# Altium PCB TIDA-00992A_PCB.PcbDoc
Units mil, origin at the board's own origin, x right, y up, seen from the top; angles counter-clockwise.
Board outline 1653.54 x 1259.84 mil, 2 copper layers (Top Layer, Bottom Layer), stack 62 mil thick; 32 components, 12 nets, 69 pads, 63 vias.
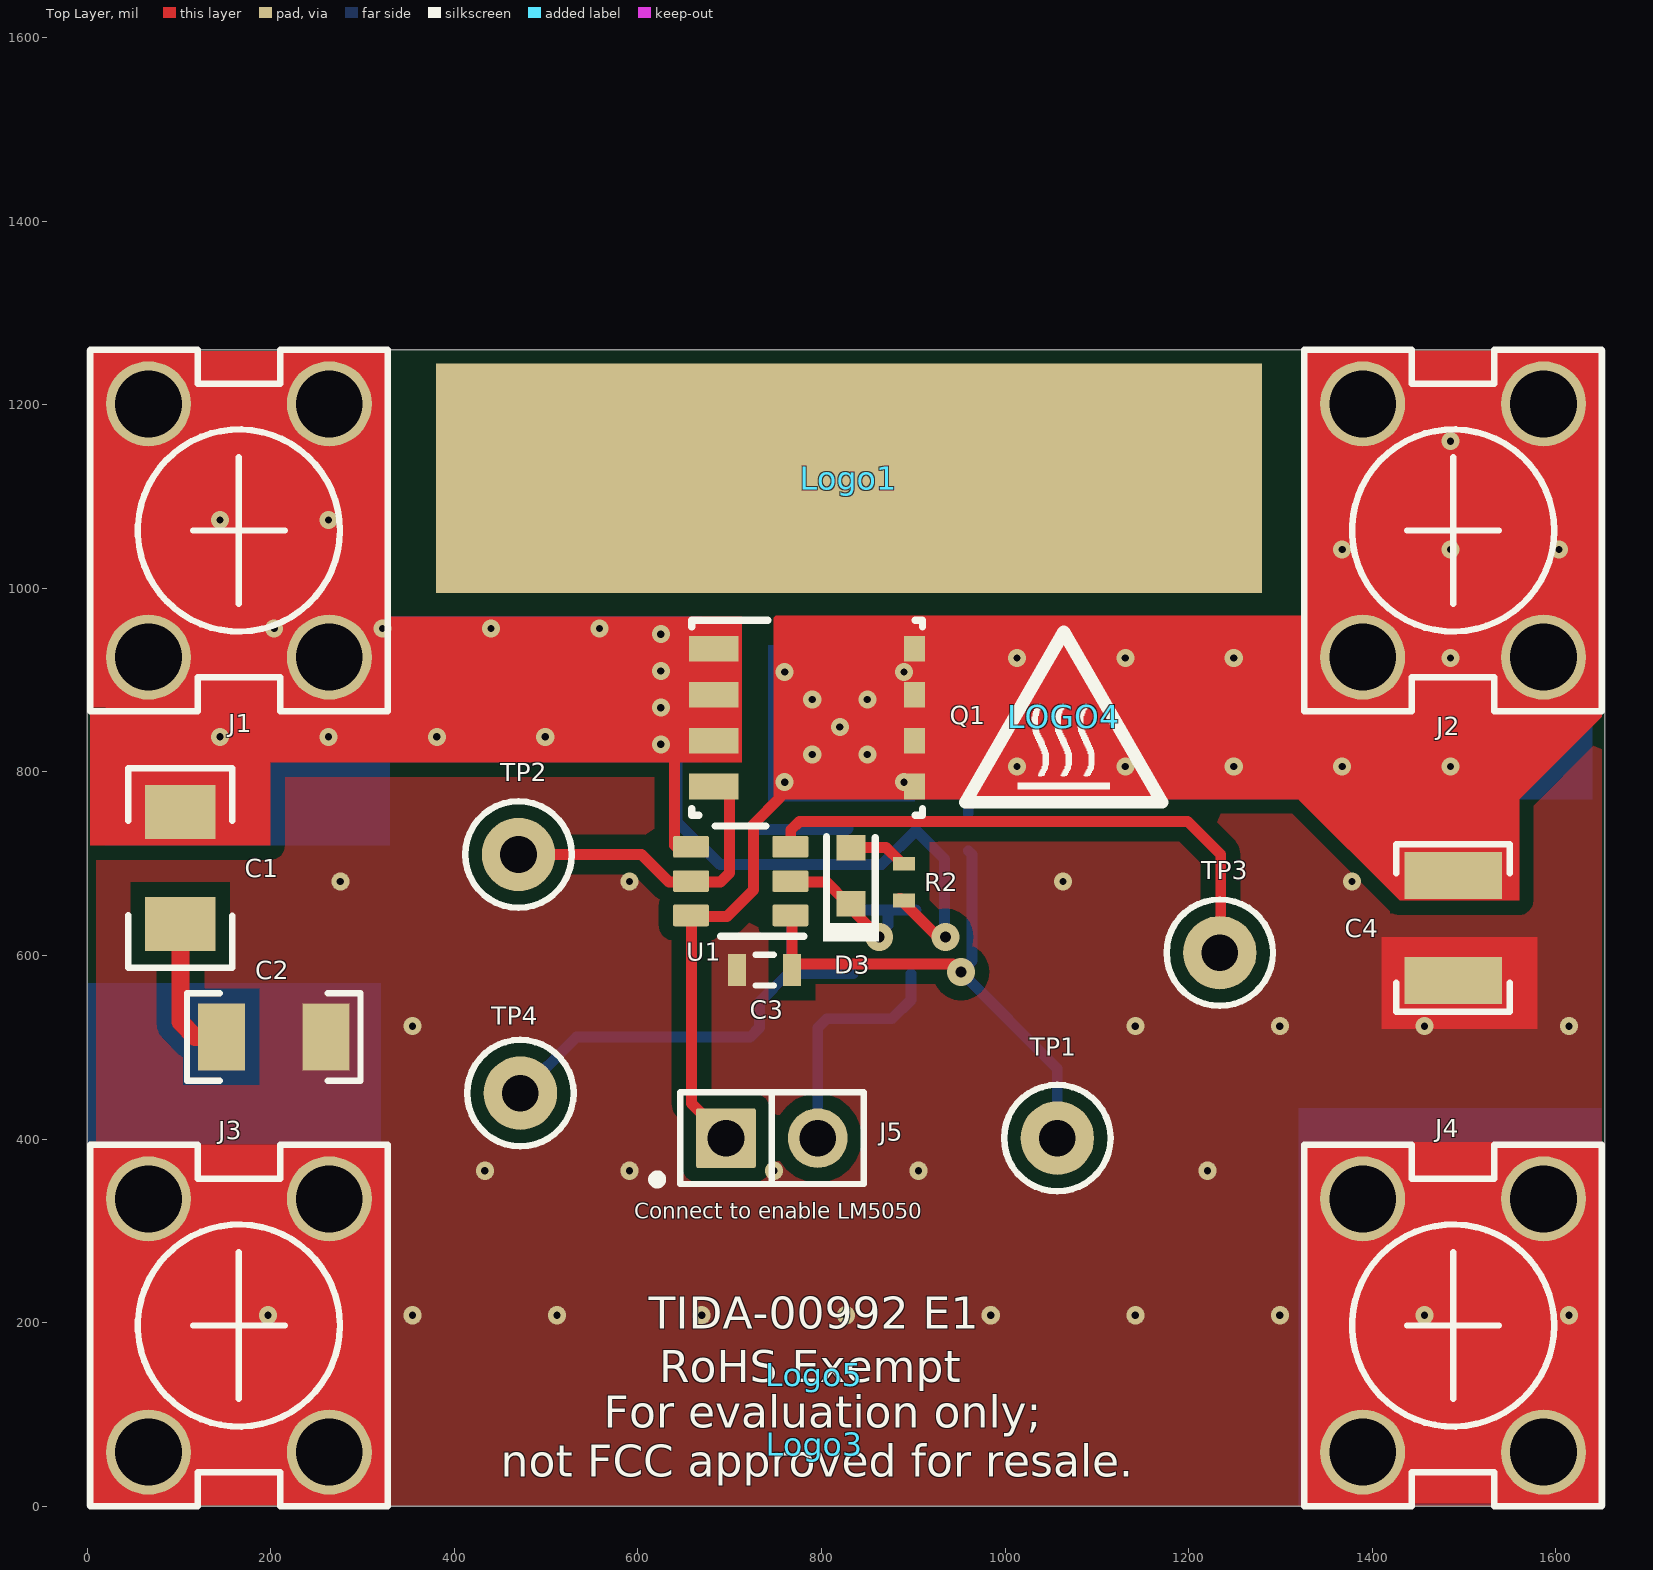
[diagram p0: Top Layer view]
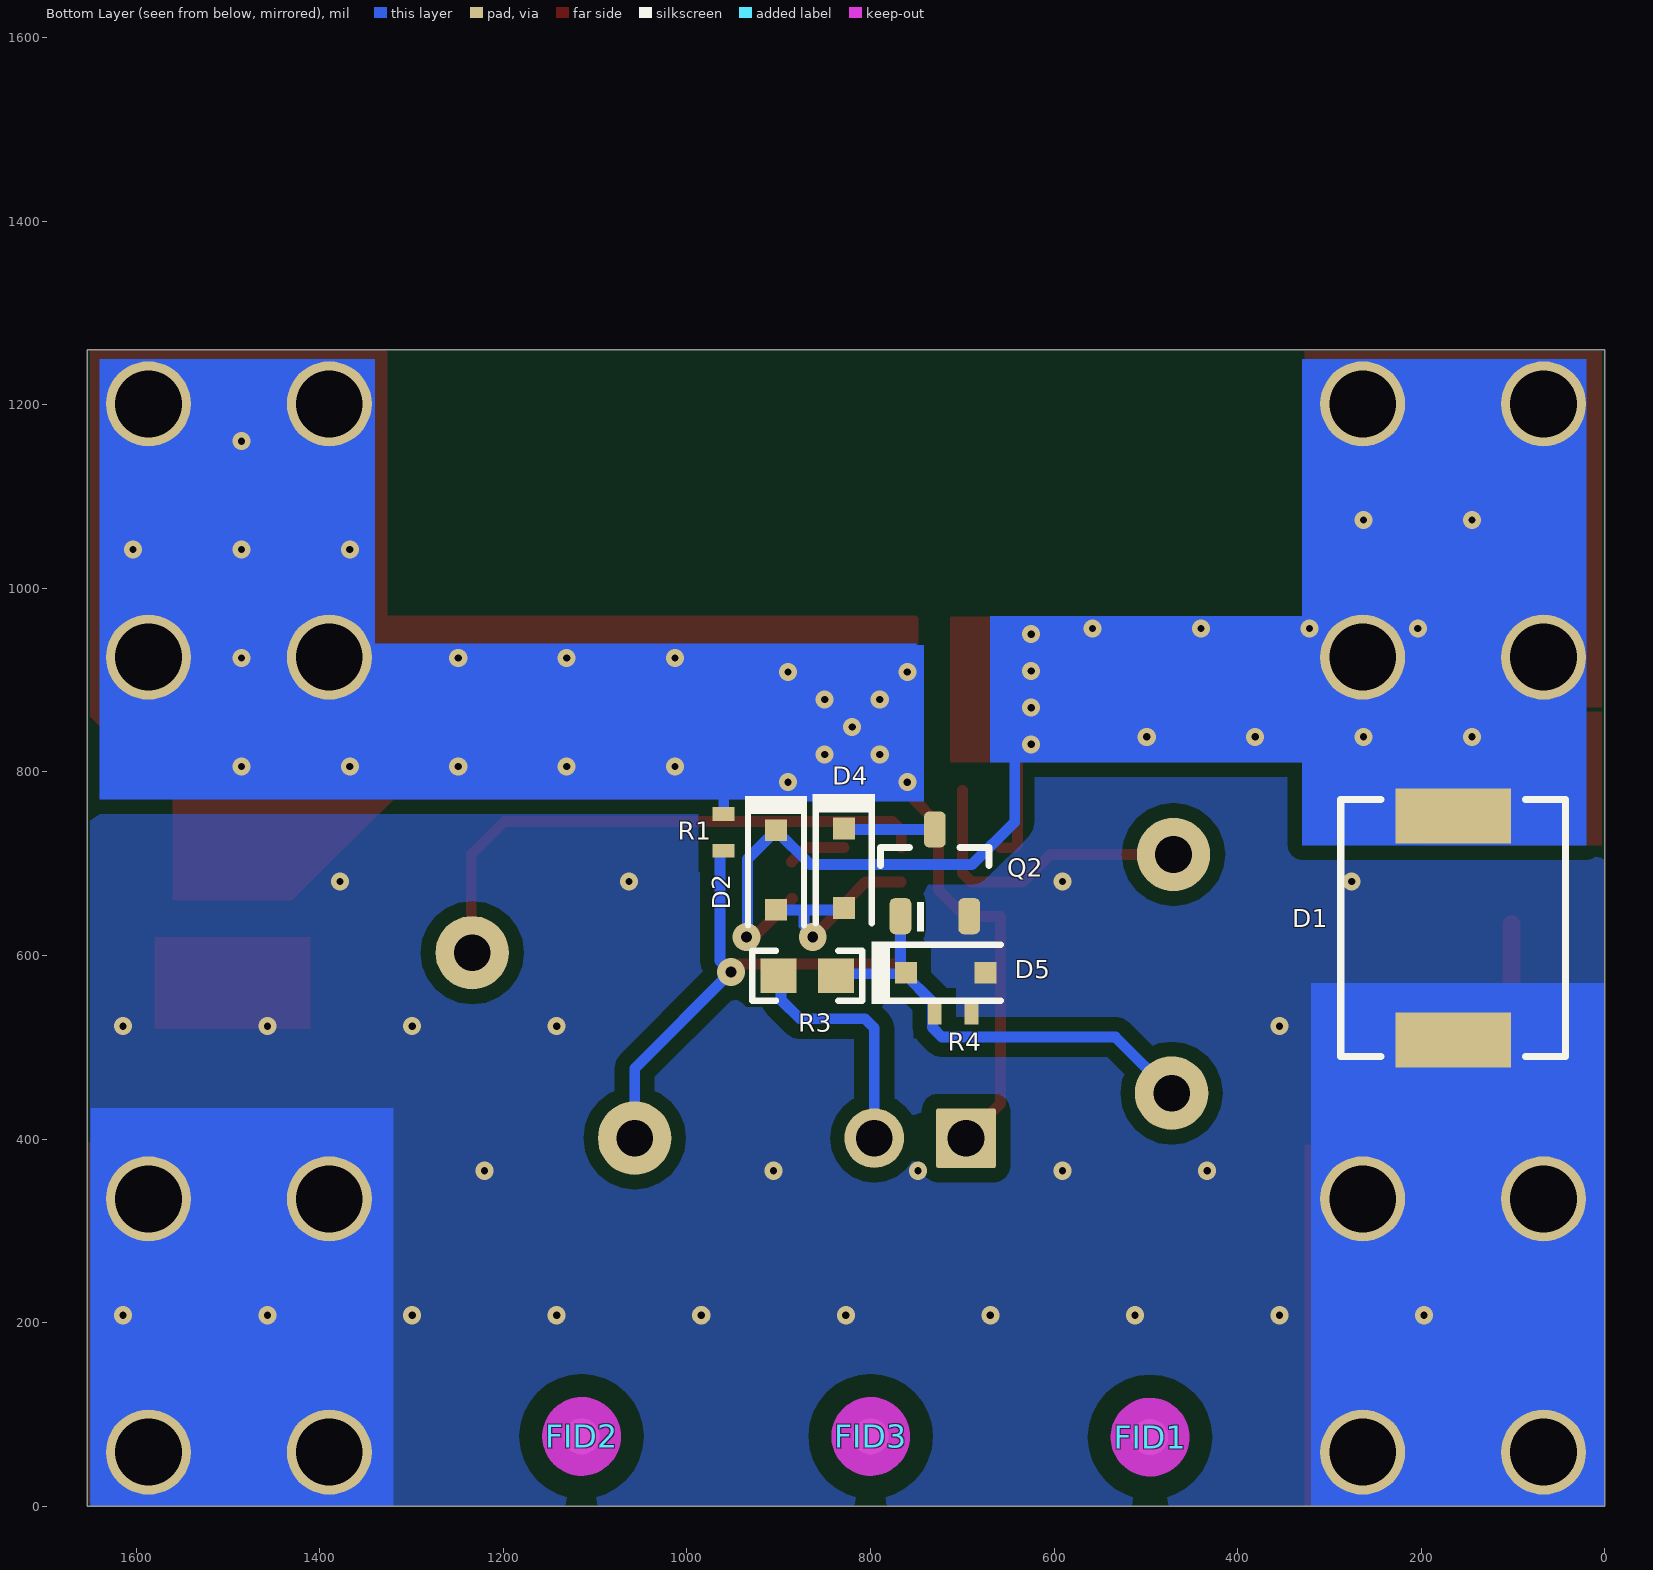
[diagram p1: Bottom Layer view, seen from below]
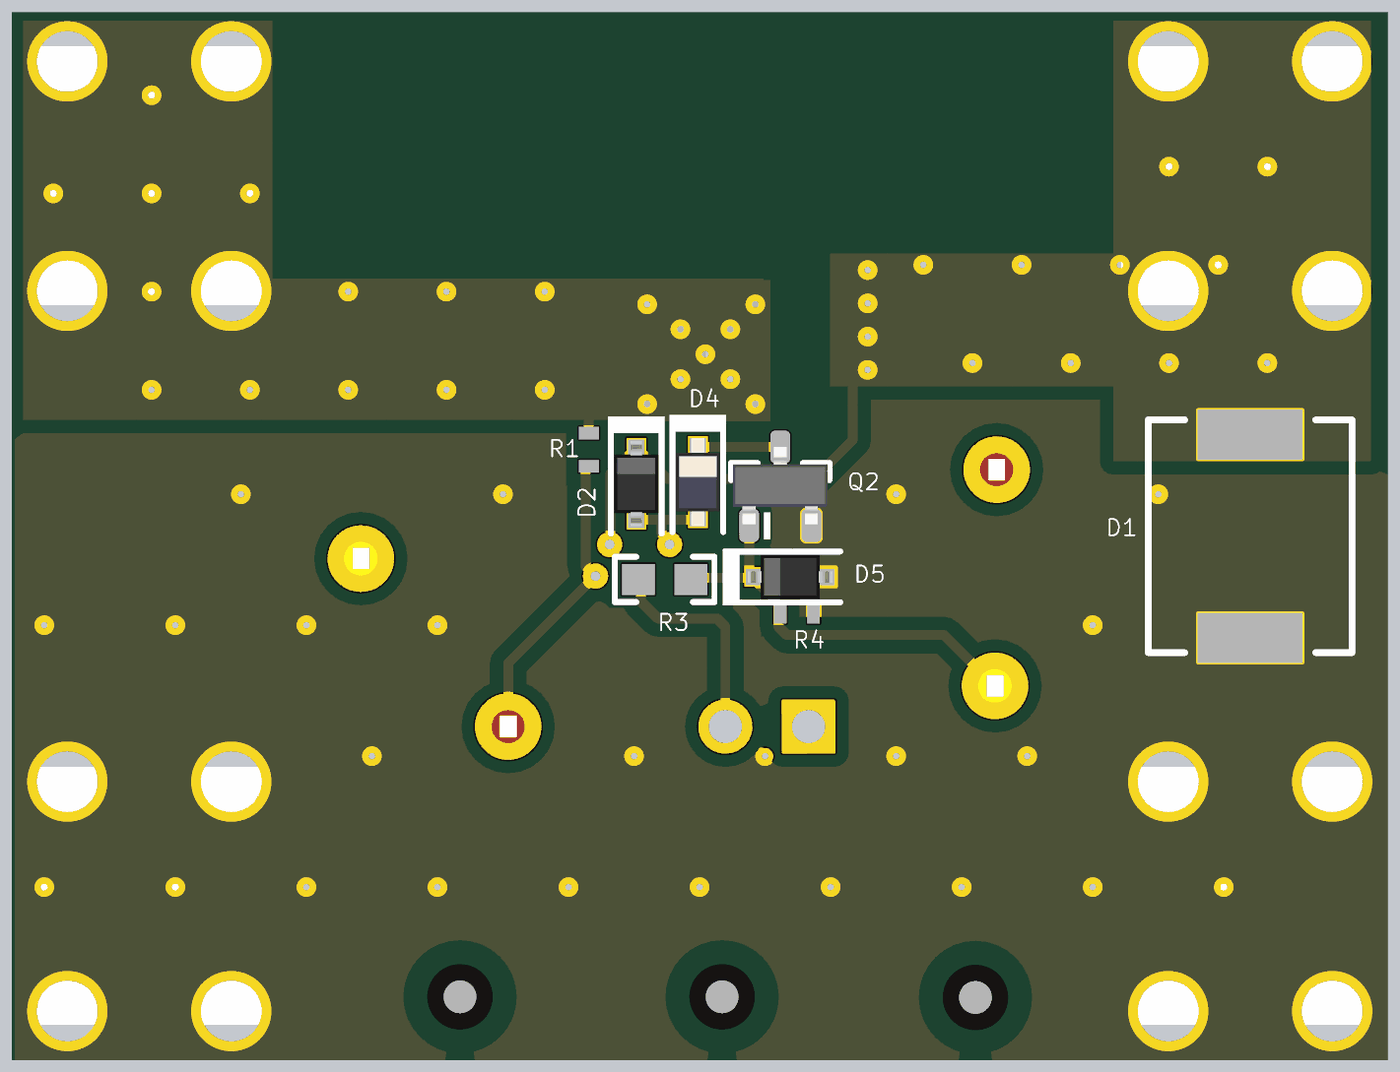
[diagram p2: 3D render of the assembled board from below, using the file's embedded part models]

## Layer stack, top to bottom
Top Solder: solder mask 0.4, Solder Resist, Dk 3.5
Top Layer: signal copper 1.4
Dielectric1: core 59.2, FR-4, Dk 4.8
Bottom Layer: signal copper 1.4
Bottom Solder: solder mask 0.4, Solder Resist, Dk 3.5

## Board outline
0,0 1653.54,0 1653.54,1259.84 0,1259.84

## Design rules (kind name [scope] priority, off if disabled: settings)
AcuteAngle [All] p1: minimum=4.50000000000000E+0001 checktracksonly=FALSE
AssemblyTestPointUsage [All] p1: valid=2
Clearance Clearance_Keepouts [((IsTrack Or IsArc) And Not InPoly) And IsFree and IsKeepOut vs ((IsTrack Or IsArc) And Not InPoly) And IsFree and IsKeepOut] p1: gap=0
Clearance Clearance_BoardEdge_MountingHoles [OnCopper and InComponentClass('Mounting Holes') vs IsKeepOut] p2: gap=40
Clearance Clearance_BoardEdge_Poly [OnCopper and InPoly vs IsKeepOut] p3: gap=25
Clearance Clearance_BoardEdge [OnCopper and Not InComponentClass('Logo') and not InComponentClass('FiducialMark') and not InRegion(1000,500,4000,800) and Not IsKeepout vs IsKeepOut] p4: gap=75
Clearance Clearance_Poly [InPolygon] p5: gap=15.75
Clearance [All] p6: gap=7.87
ComponentClearance ComponentClearance_MountingHoles_FiducialMarks [InComponentClass('Mounting Holes') vs InComponent('TP1')] p1: gap=0 collisioncheckmode=3 verticalgap=0 showdistances=FALSE
ComponentClearance ComponentClearance_Shunt [InComponentClass('Header') vs InComponentClass('Shunt')] p2: gap=0 collisioncheckmode=3 verticalgap=0 showdistances=FALSE
ComponentClearance ComponentClearance_Logo [InComponentClass('Logo')] p3: gap=19.68 collisioncheckmode=3 verticalgap=10 showdistances=FALSE
ComponentClearance ComponentClearance_ScrewToNut [(HasFootprint('NY PMS 440 0025 PH')) vs (HasFootprint('Keystone_1902C'))] p4: gap=5 collisioncheckmode=3 verticalgap=10 showdistances=FALSE
ComponentClearance ComponentClearance_MountingHoles [InComponentClass('Mounting Holes')] p5: gap=250 collisioncheckmode=3 verticalgap=100000 showdistances=FALSE
ComponentClearance ComponentClearance_SmallPassives [HasFootprint('0201*') or HasFootprint('0402*') or HasFootprint('0508') or HasFootprint('0603*') or HasFootprint('0612') or HasFootprint('0805*') or HasFootprint('0815*') or HasFootprint('0830*') or HasFootprint('1206*') or HasFootprint('1210*') or HasFootprint('1808*') or HasFootprint('1812*') or HasFootprint('1825*') or HasFootprint('2010*') or HasFootprint('2220*') or HasFootprint('2225*') or HasFootprint('2512*') or HasFootprint('2728*') or HasFootprint('3518*') vs HasFootprint('0201*') or HasFootprint('0402*') or HasFootprint('0508') or HasFootprint('0603*') or HasFootprint('0612') or HasFootprint('0805*') or HasFootprint('0815*') or HasFootprint('0830*') or HasFootprint('1206*') or HasFootprint('1210*') or HasFootprint('1808*') or HasFootprint('1812*') or HasFootprint('1825*') or HasFootprint('2010*') or HasFootprint('2220*') or HasFootprint('2225*') or HasFootprint('2512*') or HasFootprint('2728*') or HasFootprint('3518*')] p6: gap=19.68 collisioncheckmode=3 verticalgap=10 showdistances=FALSE
ComponentClearance ComponentClearance_THtoSMT [IsThruComponent vs IsSMTComponent] p7: gap=59.06 collisioncheckmode=3 verticalgap=30 showdistances=FALSE
ComponentClearance ComponentClearance_THtoTH [IsThruComponent vs IsThruComponent] p8: gap=118.11 collisioncheckmode=3 verticalgap=30 showdistances=FALSE
ComponentClearance [All] p9: gap=0 collisioncheckmode=3 verticalgap=10 showdistances=FALSE
DiffPairsRouting [All] p1: maxlimit=100 minlimit=10 mostfreqgap=10 toplayer_minwidth=15 toplayer_maxwidth=15 toplayer_prefwidth=15 bottomlayer_minwidth=15 bottomlayer_maxwidth=15 bottomlayer_prefwidth=15 maxuncoupledlength=1000
FabricationTestPointUsage TestPointUsage [All] p1: valid=2 allowmultiple=FALSE
FabricationTestpoint Testpoint [All] p1: side=3 testpointundercomponent=TRUE minsize=40 maxsize=100 preferedsize=60 minholesize=0 maxholesize=40 preferedholesize=32 testpointgrid=1 allowsidetop=TRUE allowsidebottom=TRUE usegrid=TRUE gridtolerance=0.01
FanoutControl Fanout_LCC [IsLCC] p1: bgadir=Out bgaviamode=Centered fanoutstyle=Auto fanoutdirection=Alternating viagrid=1 // Fanout_LCC (Default Rule)
FanoutControl Fanout_BGA [IsBGA] p2: bgadir=Out bgaviamode=Centered fanoutstyle=Auto fanoutdirection=Alternating viagrid=1 // Fanout_BGA (Default Rule)
FanoutControl Fanout_Default [All] p4: bgadir=Out bgaviamode=Centered fanoutstyle=Auto fanoutdirection=Alternating viagrid=1 // Fanout_Default (Default Rule)
FanoutControl Fanout_Small [(CompPinCount < 5)] p5: bgadir=Out bgaviamode=Centered fanoutstyle=Auto fanoutdirection=OutThenIn viagrid=1 // Fanout_Small (Default Rule)
HoleSize [All] p1: absolutevalues=TRUE maxlimit=251 minlimit=7.87 maxpercent=80.000 minpercent=20.000
MinimumAnnularRing MinimumAnnularRing_ThermalPadVias [IsVia and InAnyComponent] p1: minimumring=3.94
MinimumAnnularRing [All] p2: minimumring=5
MinimumSolderMaskSliver MinimumSolderMaskSliver_Logo [InComponentClass('Logo') vs InComponentClass('Logo')] p1: minsoldermaskwidth=0.7
MinimumSolderMaskSliver [All] p2: minsoldermaskwidth=4
PlaneConnect [All] p1: planeconnectstyle=Relief reliefexpansion=10 reliefentries=4 reliefconductorwidth=10 reliefairgap=10
PolygonConnect [All] p1: connectstyle=Direct reliefconductorwidth=10 reliefentries=4 polygonreliefangle="90 Angle" airgapwidth=10
RoutingVias ThermalPadVias [IsVia and InAnyComponent] p1: holewidth=7.87 width=19.68 viastyle="Through Hole" minholewidth=7.87 minwidth=19.68 maxholewidth=12.99 maxwidth=23.62
RoutingVias [All] p2: holewidth=16 width=34 viastyle="Through Hole" minholewidth=7.87 minwidth=19.68 maxholewidth=40 maxwidth=65
SilkToBoardRegionClearance [Not ((IsComment or IsDesignator) And (Hide <> 'False')) and not InRegion(1000,500,4000,800)] p1:
SilkToSilkClearance SilkToSilkClearance_Pb-FreeLogo [(HasFootprint('Pb-Free_Overlay_Medium') OR HasFootprint('Pb-Free_Overlay_Small')) vs (HasFootprint('Pb-Free_Overlay_Medium') OR HasFootprint('Pb-Free_Overlay_Small'))] p1: silktosilkclearance=0
SilkToSilkClearance [All] p2: silktosilkclearance=4
SilkToSolderMaskClearance SilkToComonentPadClearance [IsPad and InAnycomponent] p1: minsilkscreentomaskgap=0 clearancetoexposedcopper=TRUE
SilkToSolderMaskClearance "Silk to Solder Mask Opening" [All] p2: minsilkscreentomaskgap=0 clearancetoexposedcopper=TRUE
SolderMaskExpansion [All] p1: expansion=1.97
Width [All] p1: maxlimit=100 minlimit=6 preferedwidth=10 checkconnectedcopper=TRUE
15 further rules are at their usual default settings.

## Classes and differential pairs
component class Logo: Logo1
component class TIDA-00992A_Hardware: FID1 FID2 FID3 Logo1 Logo3 LOGO4 Logo5 LOGO?
component class FiducialMark: FID1 FID2 FID3
component class Header: J5
component class TIDA-00992A_AutomotiveReversePolarityProtection: C1 C2 C3 C4 D1 D2 D3 D4 D5 J1 J2 J3 J4 J5 Q1 Q2 R1 R2 R3 R4 TP1 TP2 TP3 TP4 U1

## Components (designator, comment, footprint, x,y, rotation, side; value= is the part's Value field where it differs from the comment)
C1 "VJ1206Y104KBBAT4X" 1206M 101.52,695.28 r270 top
C2 "VJ1206Y104KBBAT4X" 1206 203.32,511.34 r180 top
C3 "GRM188R72A104KA35J" 0603S 738,584 r180 top
C4 "GRM32ER71K475KE14L" 1210_270 1488.19,629.92 r270 top
D1 "1.5SMC33CA-E3/57T" DO-214AB-Bi 165.35,629.92 r90 bottom
D2 "BAS 170W E6327" sod-323 903,693 r270 bottom
D3 "LNJ337W83RA" LNJx37x8_Green 832,687 r90 top
D4 "PMEG6010CEJ,115" SOD-323F 829,695 r270 bottom
D5 "BZT52C9V1S-7-F" sod-323 718,581 r180 bottom
FID1 "Fiducial" Fiducial10-20 495.5,75.25 r180 bottom
FID2 "Fiducial" Fiducial10-20 1114.86,75.99 r180 bottom
FID3 "Fiducial" Fiducial10-20 799.9,75.99 r180 bottom
J1 "7693" 7693 165.35,1062.99 r0 top
J2 "7693" 7693 1488.19,1062.99 r0 top
J3 "7693" 7693 165.35,196.85 r0 top
J4 "7693" 7693 1488.19,196.85 r0 top
J5 "HTSW-102-07-G-S" Samtec_HTSW-102-07-G-S 746,401 r0 top
Logo1 "Texas Instruments" TI_Stacked_SolderMask_Small 830,1120 r0 top
Logo3 "FCC disclaimer" FCC_disclaimer_stacked 792.5,67.25 r0 top
LOGO4 "CAUTION HOT SURFACE" IEC_HotSurface_Small 1064,860 r0 top
Logo5 "EU RoHS Exempt Logo" EURoHS_Exempt_60mil 792.39,143.45 r0 top
Q1 "CSD19532Q5B" TRANS_NexFET_Q5B 792,859 r0 top
Q2 "NTR5198NLT1G" SOT-23 730,690 r90 bottom
R1 "CRCW040210K0FKED" 0402S 960,734 r270 bottom
R2 "CRCW040210K0FKED" 0402S 890,680 r270 top
R3 "RG1608P-203-B-T5" 0603 869,578 r180 bottom
R4 "CRCW040210K0FKED" 0402S 710,537 r0 bottom
TP1 "5000" Keystone5000 1057,401 r0 top
TP2 "5000" Keystone5000 470,710 r0 top
TP3 "5004" Keystone5004 1234,603 r0 top
TP4 "5004" Keystone5004 472,450 r0 top
U1 "LM5050Q1MKX-1/NOPB" DDC0006A_N 712,681 r180 top

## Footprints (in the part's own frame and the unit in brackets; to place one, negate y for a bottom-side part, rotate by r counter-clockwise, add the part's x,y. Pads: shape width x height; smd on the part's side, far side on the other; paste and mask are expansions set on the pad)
0402S [mil] "Based on C0402S footprint from PADS legacy"
  rect 15x24 smd: 1(-20,0) 2(20,0)
  body extent -22,-12 22,12, height 24
0603 [mm] "0603 from SM-752 data"
  rect 1x0.95 smd: 1(-0.8,0) 2(0.8,0)
  silkscreen extent -1.52,-0.69 1.52,0.69, body extent -0.87,-0.47 0.87,0.47, height 1
0603S [mil]
  rect 20x35 smd: 1(-30,0) 2(30,0)
  silkscreen extent -10,-17 10,17, body extent -34,-19 34,19, height 39
1206 [mm] "1206 from SM-752 data"
  rect 1.3x1.85 smd: 1(-1.45,0) 2(1.45,0)
  silkscreen extent -2.4,-1.21 2.4,1.21, body extent -1.7,-0.9 1.7,0.9, height 1.35
1206M [mm] "1206 from SM-752 data"
  rect 1.5x1.95 smd: 1(-1.55,0) 2(1.55,0)
  silkscreen extent -2.76,-1.44 2.76,1.44, body extent -1.7,-0.9 1.7,0.9, height 1.35
1210_270 [mm] "1210"
  rect 1.3x2.7 smd: 1(-1.45,0) 2(1.45,0)
  silkscreen extent -2.32,-1.57 2.32,1.57, body extent -1.7,-1.35 1.7,1.35, height 2.7
7693 [mm] "Keystone Electronics 7693 recommended land pattern"
  round 2.35 hole 1.85: 1(-2.502,3.505) 2(2.502,3.505) 3(-2.502,-3.505) 4(2.502,-3.505)
  silkscreen extent -4.11,-5 4.11,5, body extent -3.95,-3.94 3.95,3.96, height 8.86
DDC0006A_N [mm]
  rrect17% 1x0.6 smd: 1(-1.375,0.95) 2(-1.375,0) 3(-1.375,-0.95) 4(1.375,-0.95) 5(1.375,0) 6(1.375,0.95)
  silkscreen extent -1.75,-1.52 0.7,1.53, body extent -1.43,-1.48 1.43,1.49, height 0.92
DO-214AB-Bi [mm] "Vishay recommended land pattern 20-Dec-13"
  rect 1.52x3.2 smd: 1(-3.105,0) 2(3.105,0)
  silkscreen extent -3.55,-3.11 3.55,3.11, body extent -3.55,-3.11 3.55,3.11, height 2.62
EURoHS_Exempt_60mil [mil] "EU RoHS Exempt symbol"
FCC_disclaimer_stacked [mil]
Fiducial10-20 [mm]
  round 1 smd mask+0.5: 1(0,0)
  Top Layer keep-out circle w1.178: c0,0 r0.5
IEC_HotSurface_Small [mil]
  silkscreen extent -107,-93 107,92
Keystone5000 [mil] "For Keystone 500x miniature loop terminals"
  round 80 hole 40: 1(0,0)
  silkscreen extent -58,-58 58,58, body extent -49,-49 49,49, height 182
Keystone5004 [mil] "For Keystone 500x miniature loop terminals"
  round 80 hole 40: 1(0,0)
  silkscreen extent -58,-58 58,58, body extent -49,-49 49,49, height 182
LNJx37x8_Green [mm] "SMD, 2-Leads, Body 1.6x0.8mm"
  rect 0.7x0.8 smd: 1(0.775,0) 2(-0.775,0)
  silkscreen extent -1.83,-0.77 1.07,0.77, body extent -0.85,-0.45 0.85,0.45, height 0.25
Samtec_HTSW-102-07-G-S [mm] "Samtec 100mil, 1x2, 230 mil above insulator"
  rrect6% 1.65x1.65 hole 1.016: 1(-1.27,0)
  round 1.65 hole 1.016: 2(1.27,0)
  silkscreen extent -3.3,-1.27 2.54,1.27, body extent -2.54,-1.27 2.54,1.27, height 8.38
sod-323 [mm] "NXP recommended land pattern"
  rect 0.6x0.6 smd paste-0.05: 1(-1.1,0) 2(1.1,0)
  silkscreen extent -2.06,-0.86 1.53,0.86, body extent -1.3,-0.67 1.3,0.68, height 1.1
SOD-323F [mm] "NXP recommended land pattern"
  rect 0.6x0.6 smd paste-0.05: 1(-1.1,0) 2(1.1,0)
  silkscreen extent -2.06,-0.86 1.53,0.86, body extent -1.35,-0.67 1.35,0.67, height 0.79
SOT-23 [mm] "SOT23, 3-Leads, Body 2.9x1.3mm, Pitch 0.95mm, Lead Span 2.5mm, IPC Medium Density"
  rrect50% 1x0.6 smd: 1(-1.2,0.95) 2(-1.2,-0.95) 3(1.2,0)
  silkscreen extent -1.62,-1.5 0.7,1.5, body extent -1.16,-1.45 1.21,1.45, height 1
TI_Stacked_SolderMask_Small [mil]
  rect 900x250 smd paste-125 mask-125: 0(0,0)
TRANS_NexFET_Q5B [mm] "TI recommended land pattern (nominal) November 2012"
  rect 1.372x0.71 smd paste-0.4: 1(-2.776,1.905) 2(-2.776,0.635) 3(-2.776,-0.635) 4(-2.776,-1.905)
  rect 0.59x0.71 smd paste-0.3: 5(2.776,-1.905) 6(2.776,-0.635) 7(2.776,0.635) 8(2.776,1.905)
  Top Layer region: -1.106,-2.26 2.744,-2.26 2.744,2.26 -1.106,2.26
  silkscreen extent -3.38,-2.7 3,2.7, body extent -3.23,-2.55 2.87,2.55, height 1.06

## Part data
C1 C2: "CAP, CERM, 0.1 µF, 100 V, +/- 10%, X7R, 1206"
C3: "CAP, CERM, 0.1 µF, 100 V, +/- 10%, X7R, 0603"
C4: "CAP, CERM, 4.7 µF, 80 V, +/- 10%, X7R, 1210"
D1: "Diode, TVS, Bi, 28.2 V, 1500 W, DO-214AB (no polarity)"
D2: "Diode, Schottky, 70 V, 0.07 A, AEC-Q101, SOD-323"
D3: "LED, Green, SMD"
D4: "Diode, Schottky, 60 V, 1 A, SOD-323F"
D5: "Diode, Zener, 9.1 V, 200 mW, SOD-323"
FID1 FID2 FID3: "Fiducial mark.  There is nothing to buy or mount."
J1 J2 J3 J4: "Terminal screw, vertical, snap-in"
J5: "Header, 100mil, 2x1, Gold, TH"
Logo1: library part TI_Logo, "Texas Instrument Corporate Signature"
Logo3: library part FCC_disclaimer, "FCC_disclaimer"
LOGO4: library part IEC_HotSurface, "IEC 61010-1 Hot Surface Warning"
Logo5: library part EURoHS_Exempt
Q1: "MOSFET, N-CH, 100 V, 17 A, SON 5x6mm"
Q2: "MOSFET, N-CH, 60 V, 1.7 A, SOT-23"
R1 R2 R4: "RES, 10.0 k, 1%, 0.063 W, 0402"
R3: "RES, 20.0 k, 0.1%, 0.1 W, 0603"
TP1 TP2: "Test Point, Miniature, Red, TH"
TP3 TP4: "Test Point, Miniature, Yellow, TH"
U1: "High Side OR-ing FET Controller, DDC0006A"

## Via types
v1: diameter 19.68, hole 7.87, Top Layer to Bottom Layer, 60 vias
v2: diameter 30.32, hole 11.81, Top Layer to Bottom Layer, 3 vias

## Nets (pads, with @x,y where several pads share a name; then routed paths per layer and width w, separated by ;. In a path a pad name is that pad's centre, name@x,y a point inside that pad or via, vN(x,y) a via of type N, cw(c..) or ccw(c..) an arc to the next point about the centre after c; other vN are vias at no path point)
GND: C2.1 C3.2 C4.2 D1.1 D5.2 J3.1 J3.2 J3.3 J3.4 J4.1 J4.2 J4.3 J4.4 Q2.2 R4.1
  other v1: 197.08,208 354.56,208 512.04,208 669.52,208 827,208 984.48,208 1141.96,208 1299.44,208 1456.92,208 1614.4,208 433.3,365.48 590.78,365.48 748.26,365.48 905.74,365.48 1220.7,365.48 354.56,522.96 1141.96,522.96 1299.44,522.96 1456.92,522.96 1614.4,522.96 275.82,680.44 590.78,680.44 1063.22,680.44 1378.18,680.44
NetC1_1: C1.1 D1.2 D2.1 J1.1 J1.2 J1.3 J1.4 Q1.1 Q1.2 Q1.3 R2.2 U1.4 | length 686
  Top Layer w11.81: 640,820 640,720 642.6,717.4 U1.4@658.31,717.4 ; R2.2@886,662 884.92,662 927.45,619.48 934.48,619.48 v2(935,620)
  Bottom Layer w11.81: 643,815 643,745.5 689.5,699 865.69,699 D2.1 934.22,705.09 v2@934.22,624.72 ; v2@933.5,624 v2@938,619.5 ; v2(935,620) v2@937.5,620
  other v1: 625,830 144.77,838.2 262.88,838.2 380.99,838.2 499.1,838.2 625,870 625,910 625,950 203.83,956.31 321.94,956.31 440.05,956.31 558.16,956.31 144.77,1074.42 262.88,1074.42
NetC1_2: C1.2 C2.2 | length 158.3
  Top Layer w19.68: C1.2 101.52,527.31 117.5,511.34 C2.2
NetC3_1: C3.1 R1.2 TP1.1 U1.1 | length 601.8
  Top Layer w11.81: U1.1@766.57,642.6 768,641.17 768,593 770.46,590.54 943.46,590.54 v2(952,582)
  Bottom Layer w11.81: R1.2 963.94,710.06 963.94,593.94 v2(952,582) 1057,477 TP1.1
NetD2_2: D2.2 D3.2 D4.2 U1.2 | length 237.1
  Top Layer w11.81: U1.2@766.57,680 805.49,680 828,657.49 826.76,656.24 v2(863,620)
  Bottom Layer w11.81: D4.2 831,649.69 872.5,649.69 ; v2(863,620) 859.54,620 872.5,632.96 872.5,649.69 ; D2.2 872.5,649.69
NetD3_1: D3.1 R2.1 | length 63.4
  Top Layer w11.81: D3.1@829,717.51 870.49,717.51 R2.1@886,702
NetD4_1: D4.1 Q2.3 | length 99.4
  Bottom Layer w11.81: Q2.3 827.94,737.24 D4.1
NetD5_1: D5.1 Q2.1 R3.2 R4.2 TP4.1 | length 497.1
  Bottom Layer w11.81: TP4.1 533,511 722.07,511 732.64,521.57 732.64,549.33 D5.1@763.31,580 ; Q2.1 767.4,584.09 D5.1@763.31,580 ; R3.2@834.5,580 D5.1@763.31,580
NetJ5_2: J5.2 R3.1 | length 262.6
  Bottom Layer w11.81: J5.2 796,521 806,531 877,531 897.5,551.5 R3.1@897.5,580
NetQ1_4: Q1.4 TP2.1 U1.5 | length 336.6
  Top Layer w11.81: TP2.1 604,710 634,680 658.31,680 690,680 700,690 Q1.4@700,780
NetTP3_1: TP3.1 U1.3 | length 613.8
  Top Layer w11.81: U1.3@766.57,717.4 766.57,736.57 776,746 1199,746 1235,710 1235,604 TP3.1
V_OUT: C4.1 J2.1 J2.2 J2.3 J2.4 J5.1 Q1.5 Q1.6 Q1.7 Q1.8 R1.1 U1.6 | length 479.3
  Top Layer w11.81: J5.1 658.31,438.69 658.31,642.6 697.2,642.6 726,671.39 726,743 755,772
  Bottom Layer w11.81: R1.1 960,781 962,783
  other v1: 760,788.82 890,788.82 1013,806 1131.11,806 1249.22,806 1367.33,806 1485.44,806 790,818.82 850,818.82 820,848.82 790,878.82 850,878.82 760,908.82 890,908.82 1013,924.11 1131.11,924.11 1249.22,924.11 1485.44,924.11 1367.33,1042.22 1485.44,1042.22 1603.55,1042.22 1485.44,1160.33
pads on no net: FID1.1 FID2.1 FID3.1 Logo1.0

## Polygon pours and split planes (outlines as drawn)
GND on Top Layer "GND_L01_P000" (solid, remove dead copper, pour order 0): 3.35,1259.99 10,1253.35 10,0 1650.04,0 1650.19,-0.15 1650.19,1259.99
GND on Bottom Layer "GND_L02_P002" (solid, remove dead copper, pour order 2): 1650,1260 0,1260 0,0 830,0 1650,0

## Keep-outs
Keep-Out Layer:
  text ".Layer_Name" at 577,-858.49 h60

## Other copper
Top Layer:
  rectangle net NetC1_1: 3.35,720 200,865.99
  rectangle net GND: 1410,520 1580,620
  rectangle net NetC1_1: 3.35,870 327.35,1258.73
  rectangle net GND: 3.35,-0.15 327.35,393.85
  rectangle net GND: 1328,3 1652,397
  rectangle net V_OUT: 1326.19,865.99 1650.19,1259.99
  rectangle net NetC1_1: 20,810 713.32,969.21
  region net V_OUT: 750,970 747.97,967.97 747.97,770.28 1319.72,770.28 1430,660 1560,660 1560,770 1650,860 1650,970
  text ".Layer_Name" at 577,-858.49 h60
Bottom Layer:
  rectangle net GND: 0,0 320,570
  rectangle net GND: 1320,0 1650,433.8
  rectangle net V_OUT: 1340,780 1640,1250
  rectangle net NetC1_1: 20,720 330,1250
  rectangle net V_OUT: 742,768 902,938
  rectangle net NetC1_1: 30,810 670,970
  rectangle net V_OUT: 750,770 1640,940
  text ".Layer_Name" at 577,-858.49 h60

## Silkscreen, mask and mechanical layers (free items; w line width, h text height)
Top Overlay:
  text "Connect to enable LM5050" at 596,307 h29.53
  text "TIDA-00992 E1" at 612,182 h60
  text ".Layer_Name" at 577,-858.49 h60
Bottom Overlay:
  text ".Layer_Name" at 577,-858.49 h60
Top Paste:
  text ".Layer_Name" at 577,-858.49 h60
Bottom Paste:
  text ".Layer_Name" at 577,-858.49 h60
Top Solder:
  text ".Layer_Name" at 577,-858.49 h60
  text ".Layer_Name" at 577,-858.49 h60
Bottom Solder:
  text ".Layer_Name" at 577,-858.49 h60
Drill Guide:
  text ".Layer_Name" at 577,-858.49 h60
M1 Board Outline:
  the board outline again, w10
  text ".Layer_Name" at 577,-858.49 h60
M2 Board Dimensions:
  rectangle: 0,-275 125,-150
  rectangle: 125,-400 500,-275
  lines w7: 0,-275 1000,-275 ; 125,-400 125,-150 ; 250,-400 250,-150 ; 500,-400 500,-150 ; 750,-400 750,-150 ; 0,-400 1000,-400 1000,-150 0,-150 0,-400
  text ".Layer_Name" at 577,-858.49 h60
M3 3D STEP Top:
  text ".Layer_Name" at 577,-858.49 h60
M4 3D STEP Bottom:
  text ".Layer_Name" at 577,-858.49 h60
M5 Assembly Top:
  lines w10: -292,-930.17 6308,-930.17 ; -292,-726.83 6310,-726.83 ; -292,-523.5 -292,-1133.5 3713,-1133.5 6310,-1133.5 6310,-523.5 -291.5,-523.5 -291.5,-1133.5 1284,-1133.5 ; 2173,-1133.5 2173,-523.5 ; 3440,-726.83 3440,-523.5 ; 4280,-726.83 4280,-523.5 ; 4902,-1140 4902,-937.17
  text "COMPONENTS MARKED 'DNP' SHOULD NOT BE POPULATED." at 1153.5,-318.5 h60
  text "ASSEMBLY VARIANT:" at 1153,-434 h60
  text ".VariantName" at 2189,-434 h60
  text "PCB VIEWED FROM TOP SIDE" at -228.5,-655.67 h60
  text "BOARD #:" at 2248,-655.67 h60
  text ".PRJ_Number" at 2793.5,-655.67 h60
  text "REV:" at 3638,-655.67 h60
  text ".PCB_Rev" at 3929.5,-655.67 h60
  text "SVN REV:" at 4476,-655.67 h60
  text ".VersionControl_RevNumber" at 4982,-655.67 h60
  text "TID #:" at 2248,-859 h60
  text ".TID" at 2793.5,-859 h60
  text "PLOT NAME =" at -228.5,-1064.34 h60
  text ".plot_File_Name" at 577,-1064.34 h60
  text "GENERATED    :" at 2250,-1064.34 h60
  text ".Print_Date" at 3119.5,-1064.34 h60
  text ".Print_Time" at 3848.5,-1064.34 h60
  text "TEXAS INSTRUMENTS" at 5113,-1064.34 h60
M6 Assembly Bottom:
  lines w10: -292.5,-727.33 6309.5,-727.33 ; -290.5,-930.67 6309.5,-930.67 ; 1115.5,-1140.5 1115.5,-937.67 ; 1737.5,-727.33 1737.5,-524 ; 2577.5,-727.33 2577.5,-524 ; 3844.5,-1134 3844.5,-524 ; 4733.5,-1134 6309,-1134 6309,-524 -292.5,-524 -292.5,-1134 2304.5,-1134 6309.5,-1134 6309.5,-524
  text "COMPONENTS MARKED 'DNP' SHOULD NOT BE POPULATED." at 6102,-318 h60
  text ".VariantName" at 5058,-434 h60
  text "ASSEMBLY VARIANT:" at 6097,-434 h60
  text ".VersionControl_RevNumber" at 1035.5,-656.17 h60
  text "SVN REV:" at 1541.5,-656.17 h60
  text ".PCB_Rev" at 2088,-656.17 h60
  text "REV:" at 2379.5,-656.17 h60
  text ".PRJ_Number" at 3224,-656.17 h60
  text "BOARD #:" at 3769.5,-656.17 h60
  text "PCB VIEWED FROM BOTTOM SIDE" at 6246,-656.17 h60
  text ".TID" at 3224,-859.5 h60
  text "TID #:" at 3769.5,-859.5 h60
  text "TEXAS INSTRUMENTS" at 904.5,-1064.84 h60
  text ".Print_Time" at 2169,-1064.84 h60
  text ".Print_Date" at 2898,-1064.84 h60
  text "GENERATED    :" at 3767.5,-1064.84 h60
  text ".plot_File_Name" at 5440.5,-1064.84 h60
  text "PLOT NAME =" at 6246,-1064.84 h60
M9 Title Sheet:
  drawing of 57 lines, arcs and shapes, not listed
  text "1" at 739.84,8036.5 h70
  text "2" at 3235.5,8036.5 h70
  text "3" at 5724.84,8036.5 h70
  text "4" at 8231.51,8036.5 h70
  text "5" at 10730.5,8036.5 h70
  text "6" at 13235.5,8036.5 h70
  text "A" at -416.5,6893.5 h70
  text "A" at 14383.5,6893.5 h70
  text "B" at -416.5,4513.5 h70
  text "B" at 14383.5,4513.5 h70
  text "C" at -416.5,2138.5 h70
  text "C" at 14383.5,2138.5 h70
  text "PROJECT TITLE:" at 11343.5,277.5 h45
  text ".PRJ_Title" at 11393.5,144.17 h70
  text "DESIGNED FOR:" at 11343.5,-23.5 h45
  text ".PRJ_Customer" at 11393.5,-163.5 h70
  text "D" at -416.5,-231.5 h70
  text "D" at 14383.5,-231.5 h70
  text "FILE NAME:" at 11343.5,-323.5 h45
  text ".PCB_File_Name_No_Path" at 11393.5,-443.5 h70
  text "Texas Instruments (TI) and/or its licensors do not warrant the accuracy or completeness of this specification" at 6374,-605.34 h45
  text "ENGINEER:" at 11343.5,-613.5 h45
  text "LAYOUT BY:" at 12848.5,-613.5 h45
  text "or any information contained therein. TI and/or its licensors do not warrant that this design will meet" at 6329.01,-718 h45
  text ".PRJ_Engineer" at 11393.5,-768.49 h70
  text ".PCB_Layout" at 12899,-768.49 h70
  text "the specifications, will be suitable for your application or fit for any particular purpose, or will operate in" at 6329.01,-830.67 h45
  text ".Layer_Name" at 577,-858.49 h60
  text "ALTIUM DESIGNER VERSION:" at 12848.5,-923.5 h45
  text "an implementation. TI and/or its licensors do not warrant that the design is production worthy. You should" at 6329.01,-943.33 h45
  text "completely validate and test your design implementation to confirm the system functionality for your application." at 6374,-1056 h45
  text ".print_Scale" at 11393.5,-1056.83 h70
  text ".Application_BuildNumber" at 12899,-1056.83 h70
  text "1" at 739.84,-1263.5 h70
  text "2" at 3235.5,-1263.5 h70
  text "3" at 5724.84,-1263.5 h70
  text "4" at 8231.51,-1263.5 h70
  text "5" at 10730.5,-1263.5 h70
  text "6" at 13235.5,-1263.5 h70
M10 Fab Notes:
  drawing of 173 lines, arcs and shapes, not listed
  text "DESIGN INFORMATION" at 12377.02,6201 h60
  text "MIN. TRACK WIDTH:" at 11732.46,6021 h60
  text "8" at 12828.7,6021 h60
  text "MIL" at 12983.46,6021 h60
  text "MIN. CLEARANCE:" at 11732.46,5889 h60
  text "0.2" at 12768.7,5889 h60
  text "mm" at 12983.46,5889 h60
  text "MIN. VIA PAD SIZE:" at 11732.46,5757 h60
  text "24" at 12798.71,5757 h60
  text "MIL" at 12983.46,5757 h60
  text "0.05mm (2MIL)" at 12427.46,5615.29 h60
  text "MINIMUM ANNULAR RING" at 11403.23,5611 h60
  text "EXTERNAL" at 13135.46,5611 h60
  text "PER" at 11603.23,5493 h60
  text "IPC-D-275 CLASS 2 LEVEL C" at 11823.23,5493 h60
  text "MIL, HOLES" at 13311.46,5380.71 h60
  text "+/-" at 12919,5380 h60
  text "+/-" at 13773,5380 h60
  text "REGISTRATION TOLERANCES:" at 11403.23,5375 h60
  text "METAL" at 12603,5375 h60
  text "5" at 13179.2,5375 h60
  text "3" at 14012.2,5375 h60
  text "MIL" at 14128.46,5375 h60
  text "+/-" at 13773,5262 h60
  text "HOLE SIZE TOLERANCE (UNLESS OTHERWISE SPECIFIED):" at 11403.23,5257 h60
  text "3" at 14012.2,5257 h60
  text "MIL" at 14128.46,5257 h60
  text "MATERIAL:" at 11328.46,5047.54 h60
  text "FR-4 High Tg" at 12314.9,4907.21 h60
  text "FR-408" at 11749.46,4898.64 h60
  text "OTHER" at 13237.46,4898.64 h60
  text "X" at 12160,4895 h60
  text "62 MIL (1.6mm) +/-10%" at 12069.56,4735.92 h60
  text "THICKNESS:" at 11403.23,4731.64 h60
  text "X" at 11941.4,4731.64 h60
  text "OTHER" at 13354.46,4731.64 h60
  text "TOLERANCE:" at 11403.23,4573.64 h60
  text "X" at 12242.53,4573.64 h60
  text "ANSI IPC-6012 TYPE 3 CLASS 2" at 12429.48,4573.64 h60
  text "OTHER +/-" at 12429.46,4417.64 h60
  text "BOW & TWIST:" at 11403.23,4260.64 h60
  text "X" at 12242.53,4260.64 h60
  text "ANSI IPC-6012 TYPE 3 CLASS 2" at 12429.48,4260.64 h60
  text "OTHER +/-" at 12429.46,4102.13 h60
  text "DRILLING:" at 11328.46,3963.64 h60
  text "REFERENCE:" at 11403.23,3846.64 h60
  text "X" at 12051.46,3846.64 h60
  text "AS SHOWN" at 12238.46,3846.64 h60
  text "X" at 12952.46,3846.64 h60
  text "NC_DRILL FILES" at 13089.46,3846.64 h60
  text "PTH COPPER THICKNESS:" at 11403.23,3688.64 h60
  text "X" at 12533.46,3688.64 h60
  text "20-30 um" at 12670.46,3688.64 h60
  text "OTHER" at 13387.46,3688.64 h60
  text "BOARD FINISH:" at 11328.46,3529.64 h60
  text "SILKSCREEN:" at 11483.68,3411.64 h60
  text "X" at 12432.46,3411.64 h60
  text "TOP" at 12558.46,3411.64 h60
  text "X" at 12942.46,3411.64 h60
  text "BOTTOM" at 13069.46,3411.64 h60
  text "SILKSCREEN COLOR:" at 11483.68,3244.64 h60
  text "X" at 12431.42,3244.64 h60
  text "WHITE" at 12558.46,3244.64 h60
  text "OTHER" at 13069.46,3244.64 h60
  text "X" at 12562.42,3085.44 h60
  text "GREEN" at 12689.46,3085.44 h60
  text "OTHER" at 13307.46,3085.44 h60
  text "SOLDER RESIST COLOR:" at 11483.68,3074.64 h60
  text "X" at 12562.42,2915.44 h60
  text "MATTE" at 12689.46,2915.44 h60
  text "SEMI-GLOSS" at 13307,2914.8 h60
  text "IMMERSION GOLD (ENIG)" at 12389.46,2726.92 h60
  text "ENEPIG" at 13727,2723.64 h60
  text "SURFACE FINISH:" at 11328.46,2722.64 h60
  text "X" at 12202.51,2722.64 h60
  text "IMM. TIN/SILVER OR EQUIV" at 11658,2565.64 h60
  text "OTHER" at 13089.46,2565.64 h60
  text "ARRAY/PANEL:" at 11328.46,2386.64 h60
  text "CUT AND TRIM PER M1 BOARD OUTLINE" at 12389.46,2382.35 h60
  text "N.C. ROUTE" at 12389.46,2230.64 h60
  text "X" at 13068.46,2230.64 h60
  text "V. SCORE" at 13255.46,2230.64 h60
  text "CERTIFICATION:" at 11328.46,2093.64 h60
  text "MATERIALS AND WORKMANSHIP FOR ALL PCBS" at 12053.46,2093.64 h60
  text "TO MEET OR EXCEED THE REQUIREMENTS OF:" at 12053.46,1995.64 h60
  text "X" at 11679.96,1859.13 h60
  text "ANSI IPC-A-600F CLASS ->" at 11818.96,1859.13 h60
  text "X" at 13458.02,1859.13 h60
  text "2" at 13576.96,1859.14 h60
  text "1" at 13261.96,1857.64 h60
  text "3" at 13930.96,1857.64 h60
  text "X" at 12494.02,1699.64 h60
  text "RoHS" at 12630.96,1699.64 h60
  text "OTHER" at 13275.36,1699.64 h60
  text "PER ORDER" at 13672.42,1699.64 h60
  text "ALL BOARDS MUST MEET OR EXCEED UL94-V0 REQUIREMENTS." at 11356,1534 h60
  text "PCB MUST BEAR THE UL94V-0 UL REGISTERED MATERIAL ID NUMBER" at 11356,1414 h60
  text "ADDITIONAL REQUIREMENTS:" at 11328.46,1240.64 h60
  text "MICROSECTION:" at 11403.23,1125.64 h60
  text "YES" at 12308.96,1125.64 h60
  text "REQUIRED" at 13170.46,969.49 h60
  text "BARE BOARD ELEC. TEST:" at 11403.23,966.64 h60
  text "NONE" at 12708.96,966.64 h60
  text "X" at 13043.46,966.64 h60
  text "PER ORDER" at 13762.46,966.64 h60
  text ".Layer_Name" at 577,-858.49 h60
M11 Gerber Information:
  lines w10: -292,-930.17 6308,-930.17 ; -292,-726.83 6310,-726.83 ; -292,-523.5 -292,-1133.5 3713,-1133.5 6310,-1133.5 6310,-523.5 -291.5,-523.5 -291.5,-1133.5 1284,-1133.5 ; 2173,-1133.5 2173,-523.5 ; 3440,-726.83 3440,-523.5 ; 4280,-726.83 4280,-523.5 ; 4902,-1140 4902,-937.17
  text "ALL ARTWORK VIEWED FROM TOP SIDE" at -228.5,-655.67 h60
  text "BOARD #:" at 2248,-655.67 h60
  text ".PRJ_Number" at 2793.5,-655.67 h60
  text "REV:" at 3638,-655.67 h60
  text ".PCB_Rev" at 3929.5,-655.67 h60
  text "SVN REV:" at 4476,-655.67 h60
  text ".VersionControl_RevNumber" at 4982,-655.67 h60
  text "LAYER NAME =" at -228.5,-858.49 h60
  text "TID #:" at 2248,-859 h60
  text ".TID" at 2793.5,-859 h60
  text "PLOT NAME =" at -228.5,-1064.34 h60
  text ".plot_File_Name" at 577,-1064.34 h60
  text "GENERATED    :" at 2250,-1064.34 h60
  text ".Print_Date" at 3119.5,-1064.34 h60
  text ".Print_Time" at 3848.5,-1064.34 h60
  text "TEXAS INSTRUMENTS" at 5113,-1064.34 h60
M12 Stackup:
  drawing of 191 lines, arcs and shapes, not listed
  text "Layer" at 9790.34,7830 h60
  text "Name" at 10200.26,7830 h60
  text "Material" at 11130,7830 h60
  text "Thickness" at 11989.77,7830 h60
  text "Constant" at 12639.6,7830 h60
  text "Board Layer Stack" at 13209.46,7830 h60
  text "1" at 9790.34,7710 h60
  text "Top Overlay" at 10200.26,7710 h60
  text "2" at 9790.34,7590 h60
  text "Top Solder" at 10200.26,7590 h60
  text "Solder Resist" at 11130,7590 h60
  text "0.40mil" at 11989.77,7590 h60
  text "3.5" at 12639.6,7590 h60
  text "3" at 9790.34,7470 h60
  text "Top Layer" at 10200.26,7470 h60
  text "Copper" at 11130,7470 h60
  text "1.40mil" at 11989.77,7470 h60
  text "4" at 9790.34,7350 h60
  text "Dielectric1" at 10200.26,7350 h60
  text "FR-4" at 11130,7350 h60
  text "59.20mil" at 11989.77,7350 h60
  text "4.8" at 12639.6,7350 h60
  text "5" at 9790.34,7230 h60
  text "Bottom Layer" at 10200.26,7230 h60
  text "Copper" at 11130,7230 h60
  text "1.40mil" at 11989.77,7230 h60
  text "6" at 9790.34,7110 h60
  text "Bottom Solder" at 10200.26,7110 h60
  text "Solder Resist" at 11130,7110 h60
  text "0.40mil" at 11989.77,7110 h60
  text "3.5" at 12639.6,7110 h60
  text "7" at 9790.34,6990 h60
  text "Bottom Overlay" at 10200.26,6990 h60
  text ".Layer_Name" at 577,-858.49 h60
M13 Component Bodies Top:
  text ".Layer_Name" at 577,-858.49 h60
M14 Component Bodies Bottom:
  text ".Layer_Name" at 577,-858.49 h60
M15 Courtyards Top:
  text ".Layer_Name" at 577,-858.49 h60
M16 Courtyards Bottom:
  text ".Layer_Name" at 577,-858.49 h60
Drill Drawing:
  lines w10: 5656.09,2920.95 5711.34,2920.95 5683.72,2865.7 5656.09,2920.95 ; 5656.09,3003.83 5669.9,3003.83 5683.72,2990.02 5697.53,3003.83 5711.34,3003.83 5697.53,3017.64 5711.34,3031.46 5697.53,3031.46 5683.72,3045.27 5669.9,3031.46 5656.09,3031.46 5669.9,3017.64 5656.09,3003.83 ; 5656.09,3114.34 5656.09,3128.15 5669.9,3141.96 5656.09,3155.78 5656.09,3169.59 5669.9,3169.59 5683.72,3155.78 5697.53,3169.59 5711.34,3169.59 5711.34,3155.78 5697.53,3141.96 5711.34,3128.15 5711.34,3114.34 5697.53,3114.34 5683.72,3128.15 5669.9,3114.34 5656.09,3114.34 ; 5656.09,3238.66 5711.34,3238.66 5711.34,3293.91 5656.09,3293.91 5656.09,3238.66
  lines w12: 5606,2828.4 7584.02,2828.4 ; 5606,3325.68 7584.02,3325.68 ; 5943.86,2704.08 5943.86,3450 ; 6275.86,2704.08 6275.86,3450 ; 6912.43,2704.08 6912.43,3450 ; 7171.57,2704.08 7171.57,3450 ; 5606,2704.08 7584.02,2704.08 7584.02,3450 5606,3450 5606,2704.08
  text "Symbol" at 5680.59,3362.98 h72
  text "Quantity" at 5981.16,3362.98 h72
  text "Finished Hole Size" at 6313.16,3362.98 h72
  text "Plated" at 6949.72,3362.98 h72
  text "Hole Type" at 7208.86,3362.98 h72
  text "60" at 5981.16,3238.66 h60
  text "7.87mil (0.200mm)" at 6313.16,3238.66 h60
  text "PTH" at 6949.72,3238.66 h60
  text "Round" at 7208.86,3238.66 h60
  text "3" at 5981.16,3114.34 h60
  text "11.81mil (0.300mm)" at 6313.16,3114.34 h60
  text "PTH" at 6949.72,3114.34 h60
  text "Round" at 7208.86,3114.34 h60
  text "6" at 5981.16,2990.02 h60
  text "40.00mil (1.016mm)" at 6313.16,2990.02 h60
  text "PTH" at 6949.72,2990.02 h60
  text "Round" at 7208.86,2990.02 h60
  text "16" at 5981.16,2865.7 h60
  text "72.83mil (1.850mm)" at 6313.16,2865.7 h60
  text "PTH" at 6949.72,2865.7 h60
  text "Round" at 7208.86,2865.7 h60
  text "85 Total" at 5981.16,2741.38 h60
  text ".Layer_Name" at 577,-858.49 h60

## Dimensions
0,-400 to 1000,-400 on M2 Board Dimensions
0,0 to 0,1259.84 on M2 Board Dimensions
0,0 to 1653.54,0 on M2 Board Dimensions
